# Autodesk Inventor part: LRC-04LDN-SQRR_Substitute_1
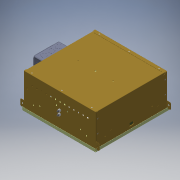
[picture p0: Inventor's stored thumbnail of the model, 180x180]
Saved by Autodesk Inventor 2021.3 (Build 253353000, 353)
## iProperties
Part Number: LRC-04LDN-SQRR_Substitute_1
Material: Generic
Document SubType Name: Modeling
Designer: JChurch
Manufacturer: Standard
Standards Organization: Custom
Density: 1 g/cm^3
Appearance: Smooth - Black
Author: JChurch
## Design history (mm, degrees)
derived "LRC-04LDN-SQRR.iam"
body "Solid9"
node "830557-00-00.iam:1::830557-PAN.ipt:1"
node "830557-00-00.iam:1::830557-FLANGE.ipt:2"
body "Solid10"
node "830557-00-00.iam:1::506010-00-38 SQUEEZED.ipt:1"
body "Solid11"
node "830557-00-00.iam:1::506010-00-38 SQUEEZED.ipt:2"
body "Solid12"
node "830557-00-00.iam:1::506010-00-38 SQUEEZED.ipt:3"
body "Solid13"
node "830557-00-00.iam:1::506010-00-38 SQUEEZED.ipt:4"
body "Solid14"
node "830557-00-00.iam:1::506010-00-38 SQUEEZED.ipt:5"
body "Solid15"
node "830557-00-00.iam:1::506010-00-38 SQUEEZED.ipt:6"
body "Solid16"
node "830557-00-00.iam:1::506010-00-38 SQUEEZED.ipt:7"
body "Solid17"
node "830557-00-00.iam:1::506010-00-38 SQUEEZED.ipt:8"
body "Solid18"
node "830557-00-00.iam:1::830557-FLANGE.ipt:3"
body "Solid19"
node "881088-00-00.iam:1::830140-00-00.ipt:1"
body "Solid20"
node "881088-00-00.iam:1::850014-00-00.iam:1::805044-00-00.ipt:1"
body "Solid21"
node "881088-00-00.iam:1::850014-00-00.iam:1::805174-00-00.ipt:1"
body "Solid22"
node "881088-00-00.iam:1::850014-00-00.iam:1::502055-00-00.ipt:1"
body "Solid23"
node "881088-00-00.iam:1::850014-00-00.iam:1::502055-00-00.ipt:2"
body "Solid24"
node "881088-00-00.iam:1::850014-00-00.iam:1::507032-00-00.ipt:1"
body "Solid25"
node "881088-00-00.iam:1::507000-00-00.ipt:1"
body "Solid26"
node "881088-00-00.iam:1::507000-00-00.ipt:2"
body "Solid27"
node "881088-00-00.iam:1::506002-00-00.ipt:1"
body "Solid28"
node "881088-00-00.iam:1::506002-00-00.ipt:2"
body "Solid29"
node "881088-00-00.iam:1::506002-00-00.ipt:3"
body "Solid30"
node "881088-00-00.iam:1::506002-00-00.ipt:4"
body "Solid31"
node "881088-00-00.iam:1::506002-00-00.ipt:5"
body "Solid32"
node "881088-00-00.iam:1::506002-00-00.ipt:6"
body "Solid33"
node "881088-00-00.iam:1::506002-00-00.ipt:7"
body "Solid34"
node "881088-00-00.iam:1::506002-00-00.ipt:8"
body "Solid35"
node "881088-00-00.iam:1::506002-00-00.ipt:9"
body "Solid36"
node "881088-00-00.iam:1::506002-00-00.ipt:10"
body "Solid37"
node "881088-00-00.iam:1::506002-00-00.ipt:11"
body "Solid38"
node "881088-00-00.iam:1::506002-00-00.ipt:12"
body "Solid39"
node "881088-00-00.iam:1::506002-00-00.ipt:13"
body "Solid40"
node "881088-00-00.iam:1::506002-00-00.ipt:14"
body "Solid41"
node "881088-00-00.iam:1::830392-01-00.iam:1::830392-00-00.ipt:1"
body "Solid42"
node "881088-00-00.iam:1::830392-01-00.iam:1::500027-00-00.ipt:1"
body "Solid43"
node "881088-00-00.iam:1::830392-01-00.iam:1::501030-00-00.ipt:1"
body "Solid44"
node "881088-00-00.iam:1::830392-01-00.iam:1::500027-00-00.ipt:2"
body "Solid45"
node "881088-00-00.iam:1::830392-01-00.iam:1::501030-00-00.ipt:2"
body "Solid46"
node "881088-00-00.iam:1::830392-01-00.iam:1::501030-00-00.ipt:3"
body "Solid47"
node "881088-00-00.iam:1::830392-01-00.iam:1::501030-00-00.ipt:4"
body "Solid48"
node "881088-00-00.iam:1::830392-01-00.iam:2::830392-00-00.ipt:1"
body "Solid49"
node "881088-00-00.iam:1::830392-01-00.iam:2::500027-00-00.ipt:1"
body "Solid50"
node "881088-00-00.iam:1::830392-01-00.iam:2::501030-00-00.ipt:1"
body "Solid51"
node "881088-00-00.iam:1::830392-01-00.iam:2::500027-00-00.ipt:2"
body "Solid52"
node "881088-00-00.iam:1::830392-01-00.iam:2::501030-00-00.ipt:2"
body "Solid53"
node "881088-00-00.iam:1::830392-01-00.iam:2::501030-00-00.ipt:3"
body "Solid54"
node "881088-00-00.iam:1::830392-01-00.iam:2::501030-00-00.ipt:4"
body "Solid55"
node "750206-00-00.iam:1::740066-00-XX.iam:1::509012-00-00.iam:1::"
body "Solid56"
node "750206-00-00.iam:1::740066-00-XX.iam:1::840076-00-00_5.75.ip"
body "Solid57"
node "750206-00-00.iam:1::740066-00-XX.iam:1::509012-00-00.iam:2::"
body "Solid58"
node "750206-00-00.iam:1::740066-00-XX.iam:1::840076-00-00_5.75.ip"
body "Solid59"
node "750206-00-00.iam:1::740066-00-XX.iam:1::509012-00-00.iam:3::"
body "Solid60"
node "750206-00-00.iam:1::740066-00-XX.iam:1::840076-00-00_5.75.ip"
body "Solid61"
node "750206-00-00.iam:1::740066-00-XX.iam:1::509012-00-00.iam:4::"
body "Solid62"
node "750206-00-00.iam:1::740066-00-XX.iam:1::840076-00-00_5.75.ip"
body "Solid63"
node "750206-00-00.iam:1::507055-00-38.ipt:1"
body "Solid64"
node "750206-00-00.iam:1::507055-00-38.ipt:2"
body "Solid65"
node "725292-00-00.ipt:1"
body "Solid66"
other parameters: "d15" = 61.595, "d16" = 9.525, "d17" = 9.525, "d35" = 5.08
